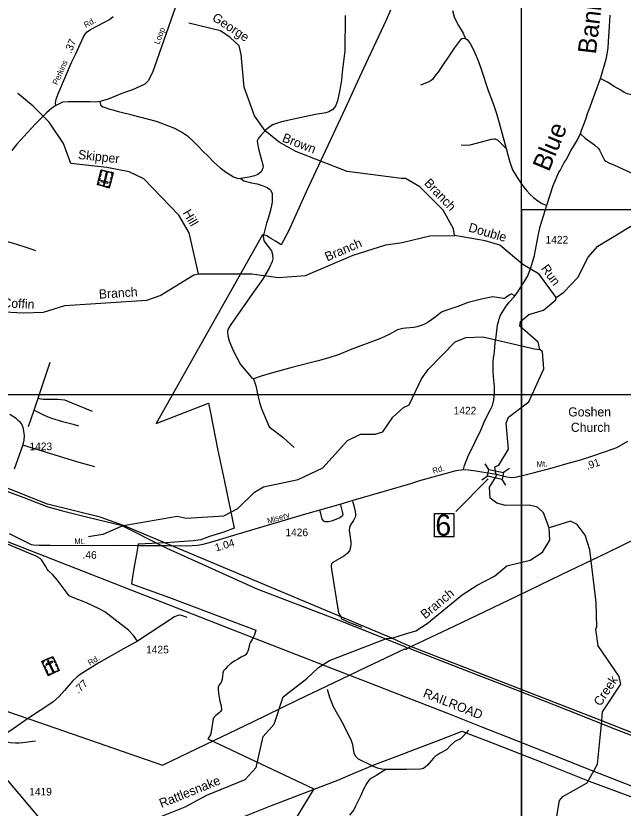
# Model space of a CAD drawing. Extents: x 2225501 to 2309677, y 165449 to 227696.
# Drawn here: x 2257951 to 2267922, y 199877 to 212881 of the extents above; entities that cross this region are included whole.
import ezdxf

# ---------------------------------------------------------------- set-up
doc = ezdxf.new("R2010")
doc.units = 0
for name, color, linetype in [('Black Area Fill Shapes', 7, 'Continuous'), ('E_RDY_CMT_EOP', 7, 'Continuous'), ('MARK ENDS WORD SYMBOL CELL', 7, 'Continuous'), ('Old_Level_3', 7, 'Continuous'), ('Old_Level_33', 7, 'Continuous'), ('Old_Level_41', 7, 'Continuous'), ('P_HYD_Drainage_Notes_Label', 7, 'Continuous'), ('P_HYD_Endwall_838_01_18_Dia_Single-Top_CELL', 7, 'Continuous'), ('P_HYD_Endwall_838_01_48_Dia_Single_CELL', 7, 'Continuous'), ('P_HYD_Pipe_Flowable_Fill', 7, 'Continuous'), ('P_HYD_Pipe_Pipe_Removal', 7, 'Continuous'), ('P_HYD_RipRap_Pad_876_02_36in_Outlet_With_Ditch-Top_CELL', 7, 'Continuous'), ('P_HYD_Table_Inlet_Data_CELL', 7, 'Continuous'), ('P_HYD_Typical_Terminator_CELL', 7, 'Continuous'), ('P_RDY_Dimension_Text', 7, 'Continuous'), ('Prop Mkg Solid Yellow Edge Line', 7, 'Continuous'), ('Prop Support', 7, 'Continuous'), ('Scratch_Level_1', 7, 'Continuous'), ('Typical Terminator CELL', 7, 'Continuous')]:
    doc.layers.add(name, color=color, linetype=linetype)

msp = doc.modelspace()

# ---------------------------------------------------------------- linework, layer by layer
at = {"layer": 'Black Area Fill Shapes'}
for p, q in [((2263777, 202753), (2264350, 202524)), ((2263712, 202194), (2264351, 202498)), ((2264350, 202521), (2264390, 202506)), ((2264350, 202479), (2264390, 202506)), ((2263799, 200571), (2263509, 200450))]:
    msp.add_line(p, q, dxfattribs=at)
for points in [[(2257817, 205072), (2257828, 205067), (2258085, 204976), (2258478, 204825), (2258739, 204751), (2259175, 204643), (2259682, 204519), (2259831, 204444), (2260234, 204242)], [(2264390, 202506), (2265041, 202813), (2265649, 203104), (2266188, 203364), (2266912, 203713), (2267652, 204070), (2268155, 204315), (2268592, 204528), (2268935, 204625), (2269528, 204791)], [(2260234, 204242), (2260387, 204165), (2260429, 204146)], [(2260429, 204146), (2261910, 203477), (2263255, 202961), (2263777, 202753)], [(2264390, 202506), (2264826, 202337), (2265541, 202059), (2266209, 201803), (2266988, 201494), (2267824, 201162), (2268489, 200903), (2269182, 200632), (2269704, 200427), (2270089, 200279)], [(2263431, 202061), (2263576, 202130), (2263712, 202194)], [(2261203, 200990), (2261843, 201296), (2262572, 201652), (2263431, 202061)], [(2257142, 201702), (2257926, 201426), (2258182, 201337)], [(2258182, 201337), (2259287, 200953), (2260358, 200584), (2261063, 200924), (2261203, 200990)], [(2264365, 200789), (2264926, 201004), (2265276, 201140), (2265343, 201114)], [(2265343, 201114), (2265814, 200932), (2266600, 200627), (2267366, 200318), (2268149, 200030), (2268810, 199775), (2268889, 199744)], [(2264365, 200784), (2263840, 200588), (2263799, 200571)], [(2263509, 200450), (2263231, 200333), (2262843, 200185)], [(2262843, 200185), (2262115, 199905), (2260829, 199388), (2259311, 198774), (2259155, 198714)]]:
    msp.add_lwpolyline(points, dxfattribs=at)
at = {"layer": 'Old_Level_3'}
for p, q in [((2258316, 206607), (2258517, 207196)), ((2258251, 206411), (2258316, 206607)), ((2258157, 206142), (2258251, 206411)), ((2265380, 201159), (2265343, 201114))]:
    msp.add_line(p, q, dxfattribs=at)
for points in [[(2263356, 212889), (2263351, 212306), (2263308, 211957), (2263295, 211832), (2263270, 211669), (2263234, 211485), (2263200, 211399), (2263157, 211343), (2263091, 211308), (2263040, 211290), (2262872, 211260), (2262489, 211177), (2262311, 211142), (2262164, 211091), (2262056, 211008), (2261971, 210919), (2261935, 210875), (2261914, 210829), (2261916, 210785), (2261933, 210697), (2262011, 210413), (2262007, 210380), (2261980, 210323), (2261926, 210279), (2261870, 210254), (2261779, 210232), (2261643, 210209)], [(2265118, 212969), (2265149, 212865), (2265164, 212827), (2265219, 212723), (2265293, 212595), (2265334, 212504)], [(2265334, 212504), (2265294, 212507), (2265272, 212503), (2265248, 212481), (2265148, 212350), (2264877, 211952), (2264843, 211905)], [(2265334, 212504), (2265344, 212504), (2265362, 212490), (2265408, 212429), (2265446, 212357), (2265486, 212273), (2265546, 212129), (2265592, 212003), (2265708, 211653), (2265793, 211426), (2265841, 211276), (2265887, 211123), (2266002, 210704)], [(2264843, 211905), (2264804, 211850), (2264790, 211835), (2264768, 211818), (2264719, 211793), (2264595, 211743)], [(2269623, 211879), (2269585, 211839), (2269442, 211724), (2269398, 211694), (2269354, 211667), (2269181, 211579), (2269140, 211563), (2269044, 211536), (2268973, 211526), (2268882, 211524), (2268706, 211529), (2268384, 211551), (2268057, 211583), (2267993, 211601), (2267941, 211624), (2267884, 211659), (2267776, 211720), (2267663, 211791), (2267554, 211847)], [(2261643, 210209), (2261609, 210206), (2261527, 210234), (2261378, 210328), (2261314, 210376), (2261191, 210491), (2261112, 210574), (2261019, 210659), (2260939, 210747), (2260860, 210826), (2260784, 210897), (2260669, 210974), (2260559, 211033), (2260334, 211122), (2260260, 211145), (2259859, 211252), (2259661, 211300), (2259565, 211329), (2259501, 211343), (2259406, 211378), (2259378, 211384), (2259358, 211396), (2259350, 211406), (2259333, 211475)], [(2267227, 210939), (2267300, 210872), (2267449, 210764), (2267515, 210703), (2267535, 210675), (2267613, 210514), (2267639, 210496), (2267687, 210471), (2267781, 210432), (2268103, 210284), (2268228, 210224), (2268355, 210157), (2268396, 210116), (2268425, 210072), (2268559, 209846), (2268620, 209748), (2268642, 209723), (2268719, 209652)], [(2266002, 210704), (2265899, 210809), (2265862, 210841), (2265850, 210848), (2265826, 210856), (2265799, 210856), (2265756, 210849), (2265404, 210759), (2265336, 210754), (2265260, 210759)], [(2266002, 210704), (2266034, 210575), (2266065, 210465), (2266086, 210401), (2266106, 210351), (2266182, 210226), (2266248, 210128), (2266290, 210068), (2266339, 210008), (2266391, 209955), (2266452, 209898), (2266521, 209843), (2266581, 209805), (2266650, 209772)], [(2261643, 210209), (2261693, 210173), (2261819, 210138), (2261911, 210121), (2261994, 210098), (2262076, 210064), (2262116, 210035), (2262130, 210021), (2262157, 209973), (2262161, 209917), (2262160, 209821), (2262137, 209711), (2262092, 209557), (2262067, 209480), (2262022, 209303)], [(2257154, 209366), (2257364, 209302), (2257603, 209236), (2257712, 209207), (2257889, 209157), (2258097, 209092), (2258199, 209056), (2258272, 209027)], [(2262022, 209303), (2262013, 209264), (2262015, 209228), (2262023, 209188), (2262148, 209025), (2262167, 208963), (2262171, 208894), (2262160, 208851), (2262111, 208737), (2262002, 208556), (2261834, 208323), (2261471, 207798), (2261429, 207732), (2261425, 207692), (2261430, 207630), (2261451, 207548), (2261514, 207397), (2261583, 207261), (2261640, 207160), (2261822, 206943), (2261854, 206924)], [(2266134, 208292), (2266096, 208311), (2266082, 208313), (2266066, 208309), (2265988, 208250), (2265975, 208244), (2265955, 208242), (2265784, 208268), (2265619, 208234), (2265376, 208175), (2265206, 208113), (2264963, 208031), (2264937, 208017), (2264829, 207930), (2264718, 207855), (2264670, 207826), (2264622, 207802), (2264540, 207774), (2264483, 207764), (2264359, 207754)], [(2264359, 207754), (2264304, 207749), (2264218, 207727), (2264079, 207653), (2263937, 207586), (2263439, 207398), (2263260, 207323), (2263090, 207268), (2262913, 207218), (2262506, 207117), (2262163, 207020), (2261977, 206967), (2261854, 206924)], [(2261854, 206924), (2261899, 206790), (2261920, 206674), (2261949, 206543), (2261981, 206447), (2262110, 206136), (2262337, 205966), (2262408, 205903), (2262519, 205795)], [(2258316, 206607), (2258362, 206597), (2258406, 206592), (2258640, 206589), (2258752, 206577), (2259203, 206394)], [(2258251, 206411), (2258396, 206336), (2258478, 206298), (2258538, 206277), (2258716, 206224), (2258891, 206180), (2258981, 206151)], [(2258062, 205842), (2258435, 205727), (2258948, 205568), (2259242, 205484)], [(2263280, 204856), (2263311, 204748), (2263319, 204699), (2263309, 204672), (2263270, 204642), (2263152, 204593), (2263084, 204579), (2263032, 204576), (2263008, 204590), (2262982, 204618), (2262947, 204755)], [(2263479, 204918), (2263508, 204824), (2263523, 204748), (2263527, 204702), (2263527, 204664), (2263492, 204598), (2263447, 204526), (2263429, 204483), (2263425, 204439), (2263432, 204365), (2263451, 204240), (2263453, 204200), (2263447, 204162), (2263428, 204100), (2263392, 204057), (2263335, 204013), (2263158, 203909), (2263136, 203889), (2263126, 203853), (2263131, 203793), (2263238, 203148), (2263248, 203091), (2263257, 203059), (2263287, 203015), (2263299, 202987), (2263323, 202973), (2263399, 202936), (2263630, 202846)], [(2259947, 202618), (2259881, 202711), (2259798, 202796), (2259410, 203099), (2259319, 203148), (2259111, 203245), (2258860, 203345), (2258828, 203364), (2258630, 203625), (2258559, 203704), (2258489, 203773), (2258466, 203799), (2258442, 203845), (2258375, 203952), (2258351, 203976), (2258275, 204016), (2258205, 204047), (2257627, 204284), (2257504, 204339)], [(2263540, 200717), (2263529, 200728), (2263507, 200780), (2263482, 200917), (2263463, 200983), (2263329, 201252), (2263167, 201542), (2263108, 201696), (2263067, 201822)], [(2265343, 201114), (2265301, 201064), (2265252, 201013), (2265160, 200972), (2265089, 200905), (2265022, 200837), (2264917, 200779), (2264867, 200749), (2264835, 200724), (2264808, 200698), (2264707, 200585), (2264642, 200526), (2264620, 200520), (2264588, 200515), (2264367, 200512), (2264023, 200510)], [(2258275, 200977), (2258064, 200947), (2258004, 200943), (2257944, 200942), (2257860, 200951), (2257804, 200961), (2257748, 200984), (2257728, 200996)], [(2263799, 200571), (2263574, 200680), (2263540, 200717)], [(2264023, 200510), (2263959, 200515), (2263887, 200533), (2263821, 200560), (2263799, 200571)], [(2264023, 200510), (2263878, 200419), (2263792, 200372), (2263758, 200346), (2263715, 200289), (2263654, 200179), (2263615, 200085), (2263530, 199908), (2263499, 199852), (2263428, 199760)]]:
    msp.add_lwpolyline(points, dxfattribs=at)
at = {"layer": 'Old_Level_33'}
for points in [[(2262890, 219654), (2262869, 219562), (2262857, 219519), (2262522, 218596), (2262202, 217703), (2262033, 217188), (2261762, 216419), (2260197, 211949), (2260121, 211814), (2260069, 211762), (2259986, 211722), (2259866, 211664), (2259693, 211606), (2259466, 211514), (2259333, 211475), (2259261, 211462), (2259169, 211468), (2258985, 211468), (2258808, 211471), (2258716, 211462), (2258607, 211410)], [(2258607, 211410), (2258602, 211448), (2258613, 211514), (2258644, 211603), (2258867, 212115), (2258934, 212258), (2259057, 212523), (2259090, 212582), (2259121, 212616), (2259178, 212656), (2259409, 212776), (2259490, 212821), (2259550, 212870)], [(2265302, 205434), (2265316, 205501), (2265385, 205668), (2265390, 205677), (2265583, 206081), (2265656, 206248), (2265745, 206419), (2265776, 206486), (2265796, 206580), (2265812, 206700), (2265811, 206802), (2265803, 206845), (2265801, 206902), (2265787, 207030), (2265787, 207088), (2265790, 207203), (2265792, 207270), (2265803, 207328), (2265807, 207370), (2265822, 207512), (2265825, 207546), (2265836, 207613), (2265861, 207808), (2265879, 207880), (2265888, 207903), (2265910, 207966), (2265990, 208099), (2266053, 208182), (2266133, 208269), (2266193, 208349), (2266246, 208437), (2266353, 208604), (2266406, 208747), (2266466, 208945), (2266524, 209272), (2266560, 209423), (2266671, 209776), (2266775, 210097), (2266865, 210313), (2266885, 210343), (2266956, 210475), (2266984, 210517), (2267069, 210677), (2267096, 210720), (2267123, 210762), (2267172, 210846), (2267219, 210949), (2267231, 210982), (2267254, 211042), (2267274, 211100), (2267314, 211202), (2267339, 211276), (2267366, 211345), (2267455, 211599), (2267548, 211855), (2267643, 212168), (2267659, 212249), (2267674, 212354), (2267681, 212457), (2267691, 212617), (2267711, 212893)], [(2258607, 211410), (2258541, 211364), (2258497, 211327), (2258457, 211291), (2258392, 211227), (2258281, 211112), (2258138, 210959), (2258037, 210850), (2257967, 210775), (2257888, 210670)], [(2257929, 205446), (2258069, 205844), (2258088, 205918), (2258092, 205987), (2258076, 206103), (2258060, 206153), (2258049, 206177), (2258027, 206207), (2257990, 206240), (2257955, 206274), (2257853, 206338)], [(2265839, 205357), (2266011, 205314), (2266095, 205306), (2266146, 205307), (2266183, 205316), (2266213, 205325), (2266291, 205341), (2266446, 205379), (2266779, 205466), (2266978, 205527), (2267203, 205591), (2267439, 205664), (2267759, 205772), (2267819, 205797), (2267998, 205902)], [(2257842, 204383), (2258205, 204207), (2258240, 204199), (2258334, 204195), (2258516, 204192), (2258962, 204190), (2259569, 204195), (2259984, 204190), (2260435, 204188), (2260751, 204183), (2260932, 204192), (2261029, 204208), (2261171, 204250), (2261586, 204372), (2262712, 204706), (2263277, 204864), (2263490, 204932), (2264057, 205096), (2264434, 205207), (2264584, 205254), (2265179, 205417), (2265302, 205434)], [(2265302, 205434), (2265385, 205429), (2265502, 205415), (2265839, 205357)], [(2260763, 203008), (2260671, 203041), (2260642, 203045), (2260612, 203040), (2260558, 203015), (2259947, 202618), (2259719, 202494), (2259313, 202263), (2259005, 202071), (2258952, 202027), (2258879, 201959), (2258751, 201809), (2258663, 201710), (2258560, 201618), (2258144, 201341), (2257867, 201150), (2257526, 200928), (2257406, 200835)], [(2260177, 196311), (2260246, 196457), (2260249, 196467), (2260283, 196565), (2260294, 196619), (2260313, 196715), (2260321, 196771), (2260328, 196869), (2260321, 196979), (2260313, 197083), (2260289, 197201), (2260250, 197307), (2260204, 197416), (2260102, 197588), (2259969, 197740), (2259181, 198716), (2257442, 200774), (2257406, 200835)]]:
    msp.add_lwpolyline(points, dxfattribs=at)
at = {"layer": 'Old_Level_41'}
msp.add_lwpolyline([(2257541, 204355), (2261853, 202675), (2263431, 202061), (2263685, 201962), (2264357, 201700), (2265036, 201436), (2265586, 201218), (2266169, 200989), (2266778, 200746), (2267396, 200499), (2268070, 200237)], dxfattribs=at)
at = {"layer": 'P_HYD_Drainage_Notes_Label'}
for p, q in [((2265716, 205435), (2265654, 205530)), ((2265693, 205324), (2265599, 205262)), ((2266054, 205449), (2265959, 205387)), ((2265998, 205179), (2265936, 205273))]:
    msp.add_line(p, q, dxfattribs=at)
msp.add_lwpolyline([(2265936, 205273), (2265693, 205324), (2265717, 205437), (2265959, 205387)], close=True, dxfattribs=at)
at = {"layer": 'P_HYD_Endwall_838_01_18_Dia_Single-Top_CELL'}
msp.add_line((2265705, 205282), (2265172, 204748), dxfattribs=at)
msp.add_lwpolyline([(2264826, 204711), (2265143, 204711), (2265143, 204332), (2264826, 204332)], close=True, dxfattribs=at)
at = {"layer": 'P_HYD_Endwall_838_01_48_Dia_Single_CELL'}
for points in [[(2264103, 212972), (2264033, 212808), (2263737, 212179), (2263560, 211801), (2263359, 211360), (2262720, 209990), (2262428, 209345), (2262309, 209121), (2262212, 209181), (2262138, 209228), (2262074, 209269), (2262002, 209287), (2260253, 206190), (2261115, 206525), (2261152, 206338), (2261264, 205776), (2261376, 205238), (2261538, 204472), (2261365, 204409), (2261133, 204334), (2260990, 204283), (2260863, 204264), (2260709, 204253), (2260414, 204234), (2259960, 204212), (2259954, 204178), (2259931, 204044), (2259898, 203873), (2259871, 203711), (2259848, 203558), (2260472, 203333), (2261890, 202801), (2261872, 202720), (2261855, 202689), (2261830, 202645), (2261801, 202604), (2261787, 202570), (2261777, 202506), (2261766, 202471), (2261748, 202426), (2261718, 202389), (2261652, 202357), (2261595, 202323), (2261534, 202287), (2261476, 202248), (2261426, 202200), (2261386, 202159), (2261360, 202132), (2261349, 202100), (2261342, 202044), (2261336, 201993), (2261322, 201940), (2261290, 201899), (2261271, 201865), (2261271, 201829)], [(2261271, 201829), (2261279, 201759), (2261302, 201633), (2261320, 201556), (2261325, 201493), (2261312, 201464), (2261287, 201442), (2261233, 201396), (2261190, 201346), (2261179, 201274), (2261156, 201134), (2261146, 201080), (2261103, 201013), (2262842, 200192), (2261366, 197773)]]:
    msp.add_lwpolyline(points, dxfattribs=at)
at = {"layer": 'P_HYD_Pipe_Pipe_Removal'}
for points in [[(2243856, 191238), (2266254, 191238), (2266254, 223234), (2243856, 223234)], [(2266254, 165449), (2309677, 165449), (2309677, 209697), (2266254, 209697)]]:
    msp.add_lwpolyline(points, close=True, dxfattribs=at)
at = {"layer": 'P_HYD_RipRap_Pad_876_02_36in_Outlet_With_Ditch-Top_CELL'}
for points in [[(2264103, 212972), (2264033, 212808), (2263737, 212179), (2263560, 211801), (2263359, 211360), (2262720, 209990), (2262428, 209345), (2262309, 209121), (2262212, 209181), (2262138, 209228), (2262074, 209269), (2262002, 209287), (2260253, 206190), (2261115, 206525), (2261152, 206338), (2261264, 205776), (2261376, 205238), (2261538, 204472), (2261365, 204409), (2261133, 204334), (2260990, 204283), (2260863, 204264), (2260709, 204253), (2260414, 204234), (2259960, 204212), (2259954, 204178), (2259931, 204044), (2259898, 203873), (2259871, 203711), (2259848, 203558), (2260472, 203333), (2261890, 202801), (2261872, 202720), (2261855, 202689), (2261830, 202645), (2261801, 202604), (2261787, 202570), (2261777, 202506), (2261766, 202471), (2261748, 202426), (2261718, 202389), (2261652, 202357), (2261595, 202323), (2261534, 202287), (2261476, 202248), (2261426, 202200), (2261386, 202159), (2261360, 202132), (2261349, 202100), (2261342, 202044), (2261336, 201993), (2261322, 201940), (2261290, 201899), (2261271, 201865), (2261271, 201829)], [(2261271, 201829), (2261279, 201759), (2261302, 201633), (2261320, 201556), (2261325, 201493), (2261312, 201464), (2261287, 201442), (2261233, 201396), (2261190, 201346), (2261179, 201274), (2261156, 201134), (2261146, 201080), (2261103, 201013), (2262842, 200192), (2261366, 197773)]]:
    msp.add_lwpolyline(points, dxfattribs=at)
at = {"layer": 'P_HYD_Typical_Terminator_CELL'}
msp.add_line((2244657, 206666), (2298327, 206666), dxfattribs=at)
at = {"layer": 'Prop Mkg Solid Yellow Edge Line'}
for points in [[(2259486, 210059), (2259293, 210107), (2259354, 210354), (2259548, 210306)], [(2259348, 210281), (2259338, 210239), (2259326, 210241), (2259337, 210284)], [(2259386, 210346), (2259384, 210335), (2259362, 210340), (2259353, 210301), (2259342, 210303), (2259354, 210354)], [(2259388, 210113), (2259406, 210109), (2259454, 210306), (2259436, 210310)], [(2259489, 210308), (2259407, 210329), (2259409, 210340), (2259492, 210320)], [(2259515, 210314), (2259513, 210303), (2259534, 210297), (2259524, 210258), (2259535, 210255), (2259548, 210306)], [(2259303, 210149), (2259314, 210146), (2259307, 210115), (2259346, 210105), (2259343, 210094), (2259293, 210107)], [(2259332, 210217), (2259322, 210175), (2259311, 210177), (2259321, 210220)], [(2259463, 210135), (2259468, 210153), (2259353, 210181), (2259349, 210163)], [(2259515, 210173), (2259504, 210131), (2259493, 210133), (2259504, 210175)], [(2259531, 210238), (2259520, 210196), (2259509, 210199), (2259520, 210241)], [(2259414, 210076), (2259364, 210089), (2259367, 210100), (2259417, 210088)], [(2259497, 210101), (2259486, 210103), (2259478, 210072), (2259439, 210082), (2259436, 210071), (2259486, 210059)], [(2258377, 202284), (2258558, 202367), (2258665, 202136), (2258484, 202053)], [(2258445, 202315), (2258492, 202337), (2258496, 202326), (2258449, 202305)], [(2258576, 202328), (2258566, 202323), (2258553, 202353), (2258516, 202336), (2258511, 202346), (2258558, 202367)], [(2258396, 202245), (2258406, 202249), (2258392, 202279), (2258429, 202296), (2258424, 202306), (2258377, 202284)], [(2258427, 202177), (2258408, 202217), (2258419, 202221), (2258437, 202182)], [(2258443, 202239), (2258451, 202222), (2258558, 202272), (2258550, 202289)], [(2258489, 202303), (2258472, 202295), (2258557, 202111), (2258574, 202119)], [(2258597, 202257), (2258578, 202296), (2258589, 202301), (2258607, 202262)], [(2258624, 202197), (2258606, 202236), (2258616, 202241), (2258635, 202202)], [(2258455, 202116), (2258437, 202156), (2258447, 202160), (2258465, 202121)], [(2258514, 202067), (2258509, 202077), (2258489, 202068), (2258472, 202105), (2258462, 202100), (2258484, 202053)], [(2258531, 202087), (2258608, 202123), (2258613, 202113), (2258536, 202077)], [(2258635, 202122), (2258630, 202133), (2258650, 202142), (2258633, 202179), (2258643, 202183), (2258665, 202136)]]:
    msp.add_lwpolyline(points, close=True, dxfattribs=at)
at = {"layer": 'Prop Support'}
for p, q in [((2264122, 202668), (2259717, 204515)), ((2264349, 202563), (2264122, 202668)), ((2267570, 201312), (2264349, 202563))]:
    msp.add_line(p, q, dxfattribs=at)
for points in [[(2259717, 204515), (2259333, 204654), (2258473, 204864), (2251395, 207679)], [(2264315, 206453), (2264406, 206497), (2264611, 206923), (2264718, 207075), (2265163, 207528), (2265337, 207604), (2265620, 207615), (2266464, 207415), (2266555, 207406)], [(2259717, 204515), (2260599, 204672), (2260749, 204639), (2261365, 204677), (2261597, 204797), (2261870, 205064), (2262019, 205149), (2262585, 205270), (2262991, 205465), (2263396, 205910), (2263612, 206014), (2263853, 206016), (2263978, 206056), (2264142, 206292), (2264315, 206453)], [(2259717, 204515), (2259377, 204371), (2259146, 204329)], [(2284408, 194805), (2272002, 199563), (2267570, 201312)]]:
    msp.add_lwpolyline(points, dxfattribs=at)
at = {"layer": 'Typical Terminator CELL'}
msp.add_line((2264122, 202668), (2264348, 202739), dxfattribs=at)
for points in [[(2266822, 208260), (2266946, 208343), (2267177, 208588), (2267349, 208922), (2267506, 209100), (2268176, 209503), (2268409, 209564), (2268951, 209478), (2269293, 209498), (2269740, 209735), (2269951, 210381), (2270050, 210464), (2270491, 210508), (2270657, 210577), (2270880, 210730), (2271246, 210857), (2271353, 210960), (2271402, 211044), (2271530, 211678), (2271835, 212040), (2271953, 212713), (2272073, 213255)], [(2264282, 210209), (2263393, 210325), (2262549, 210653), (2262273, 210809), (2262047, 210991), (2261870, 211237), (2261699, 211712), (2261653, 212245), (2261619, 212386), (2261468, 212527), (2261309, 212632), (2260791, 212763)], [(2260949, 208647), (2260794, 209322), (2260625, 209611), (2260054, 210206), (2259811, 210322), (2259444, 210392), (2258852, 210456), (2258733, 210786), (2258497, 211135), (2258237, 211399), (2257985, 211604)], [(2265155, 209277), (2265137, 209385), (2264968, 209690), (2264581, 210072), (2264347, 210211), (2264282, 210209)], [(2264291, 209160), (2264747, 209272), (2265155, 209277)], [(2266822, 208260), (2266544, 208640), (2266276, 208802), (2265898, 209118), (2265655, 209188), (2265155, 209277)], [(2260949, 208647), (2261824, 208646), (2262266, 208585), (2262707, 208619), (2263488, 208952), (2264028, 209122), (2264291, 209160)], [(2256948, 208066), (2258072, 208008), (2258406, 208018), (2258755, 208129), (2260103, 208217), (2260319, 208292), (2260875, 208632), (2260949, 208647)], [(2266555, 207406), (2266529, 207525), (2266227, 207786), (2266234, 207862), (2266375, 207980), (2266616, 208048), (2266814, 208218), (2266822, 208260)], [(2266708, 204477), (2266614, 204725), (2266513, 204816), (2266379, 204848), (2265988, 204846), (2265846, 204885), (2265737, 204965), (2265727, 205143), (2265838, 205320), (2265841, 205341), (2265839, 205355), (2265837, 205362), (2265835, 205369), (2265827, 205386), (2265825, 205397), (2265825, 205420), (2265823, 205439), (2265817, 205481), (2265881, 205508), (2266037, 205770), (2266000, 206194), (2266041, 206294), (2266372, 206547), (2266617, 207090), (2266597, 207366), (2266555, 207406)], [(2267570, 201312), (2267585, 201459), (2267881, 201913), (2267855, 202038), (2267509, 202543), (2267473, 202816), (2267489, 202852), (2267477, 203252), (2267377, 204117), (2267300, 204358), (2267165, 204531), (2267056, 204589), (2266708, 204477)], [(2264348, 202739), (2264516, 202788), (2264706, 202909), (2265277, 203380), (2265525, 203539), (2265807, 203685), (2266014, 203855), (2266396, 203949), (2266595, 204076), (2266718, 204277), (2266708, 204477)], [(2260264, 199712), (2260729, 199900), (2261086, 200093), (2261717, 200350), (2261899, 200543), (2262011, 201053), (2262193, 201253), (2262339, 201702), (2262728, 202006), (2262918, 202183), (2263100, 202301), (2264039, 202660), (2264122, 202668)], [(2266959, 196289), (2266940, 196598), (2266988, 196790), (2267152, 197059), (2267059, 198091), (2267027, 198849), (2266924, 199140), (2266605, 199435), (2266604, 199543), (2266778, 199661), (2266835, 199745), (2266874, 200003), (2266932, 200071), (2267330, 200293), (2267502, 200601), (2267570, 201312)]]:
    msp.add_lwpolyline(points, dxfattribs=at)

# ---------------------------------------------------------------- texts
at = {"layer": 'E_RDY_CMT_EOP'}
for s, p in [('1422', (2266648, 209144)), ('1422', (2265139, 206339)), ('1423', (2258175, 205752)), ('1426', (2262377, 204341)), ('1425', (2260090, 202418)), ('1419', (2258171, 200085))]:
    msp.add_text(s, height=125, dxfattribs=at).set_placement(p)
at = {"layer": 'MARK ENDS WORD SYMBOL CELL'}
for s, height, rotation, p in [('Bank', 300, 83.2952, (2267473, 212243)), ('Rd.', 95, 29.369, (2259101, 212680)), ('Loop', 95, 69.4507, (2260304, 212403)), ('Perkins', 95, 65.896, (2258633, 211738)), ('Blue', 300, 67.5203, (2266702, 210310)), ('Rd.', 95, 16.6076, (2264807, 205364)), ('Mt. ', 95, 6.243, (2266506, 205470)), ('Misery', 95, 17.2934, (2262095, 204542)), ('Mt.', 95, 0.2875, (2258911, 204211)), ('Rd.', 95, 30.5309, (2259169, 202213))]:
    msp.add_text(s, height=height, rotation=rotation, dxfattribs=at).set_placement(p)
at = {"layer": 'P_HYD_Endwall_838_01_18_Dia_Single-Top_CELL'}
msp.add_text('6', height=350, dxfattribs=at).set_placement((2264838, 204348))
at = {"layer": 'P_HYD_Pipe_Flowable_Fill'}
msp.add_text('RAILROAD', height=150, rotation=338.4309, dxfattribs=at).set_placement((2264625, 201708))
at = {"layer": 'P_HYD_Table_Inlet_Data_CELL'}
for s, p in [('Goshen', (2267020, 206306)), ('Church', (2267063, 206053))]:
    msp.add_text(s, height=150, dxfattribs=at).set_placement(p)
at = {"layer": 'P_RDY_Dimension_Text'}
for s, rotation, p in [('.37', 66.7843, (2258857, 212254)), ('.91', 18.6012, (2267332, 205430)), ('1.04', 16.2808, (2261240, 204089)), ('.46', 358.8382, (2259045, 203974)), ('.77', 43.1652, (2258977, 201748))]:
    msp.add_text(s, height=125, rotation=rotation, dxfattribs=at).set_placement(p)
at = {"layer": 'Scratch_Level_1'}
for s, rotation, p in [('George', 326.6254, (2261161, 212816)), ('Brown', 338.7591, (2262312, 210822)), ('Skipper', 353.8294, (2258967, 210533)), ('Branch', 313.6489, (2264645, 210125)), ('Hill', 300.3396, (2260686, 209650)), ('Double', 343.8624, (2265371, 209345)), ('Branch', 23.0572, (2263063, 208849)), ('Run', 306.2432, (2266565, 208733)), ('Branch', 3.7565, (2259319, 208238)), ('Coffin', 357.0462, (2257729, 208098)), ('Branch', 39.5158, (2264672, 202975)), ('Creek', 56.8741, (2267551, 201540)), ('Rattlesnake', 21.9859, (2260342, 199879))]:
    msp.add_text(s, height=150, rotation=rotation, dxfattribs=at).set_placement(p)

doc.saveas('drawing.dxf')
